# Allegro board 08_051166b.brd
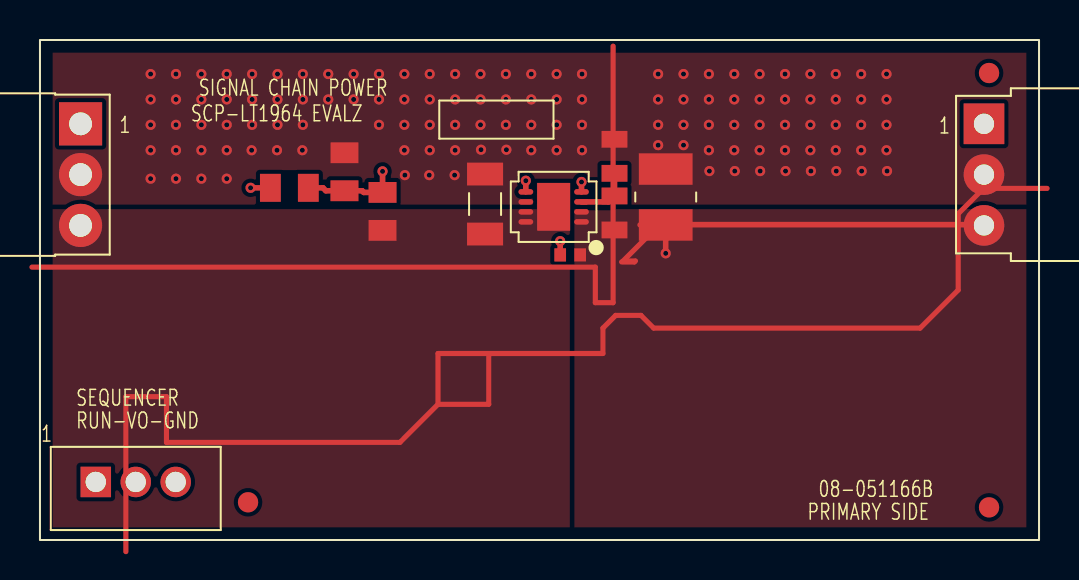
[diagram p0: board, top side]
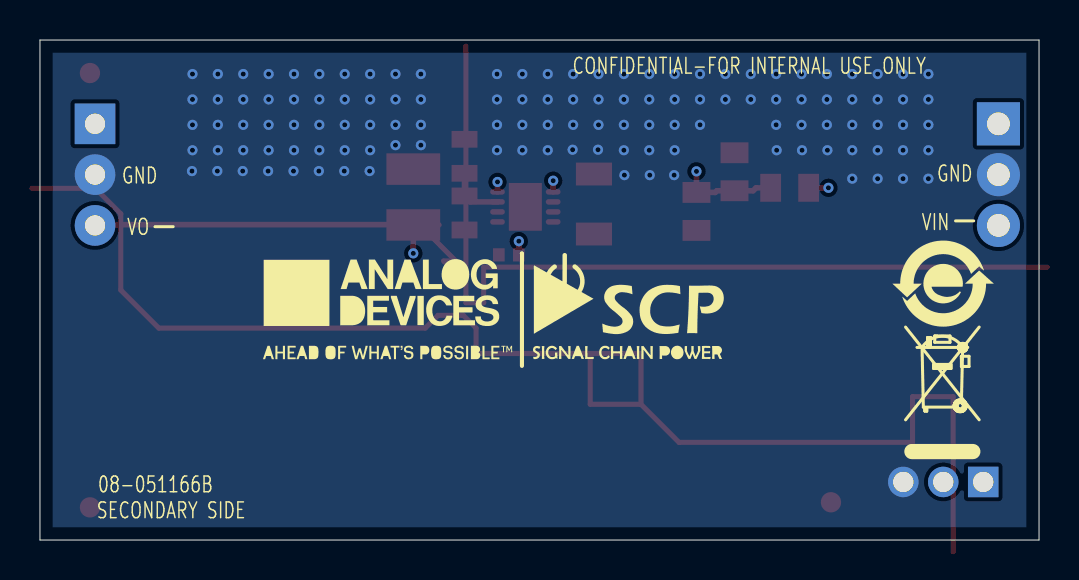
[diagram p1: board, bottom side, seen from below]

Outline 50 x 25 mm; copper layers: TOP, L2_GND, L3_SIG, BOTTOM. Coordinates in mm from the lower left corner of the outline.
Outline path: 0,25 50,25 50,0 0,0 0,25

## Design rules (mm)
constraint set DEFAULT: min track width 0.203

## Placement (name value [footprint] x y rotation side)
C3  0.01uF  [C0402]  26.54 14.26 0 top
C4  1UF  [C1206]  22.28 16.8 90 top
C5  10uF  [C1210-2]  31.32 17.15 270 top
INPUT  PBC03SBAN  [CNTHMHDRRA1X3L300W100H145]  2.03 20.81 270 top
NOREF  -  [unnamed]  47.5 23.35 0 top
NOREF#2  -  [#2]  -241.7 -190.28 0 top
NOREF#3  -  [unnamed]  10.41 1.89 0 top
NOREF#4  -  [#2]  90.79 32.31 0 top
NOREF#5  -  [#2]  -150.79 -17.34 0 top
NOREF#6  -  [#2]  -349.65 -285.95 0 top
NOREF#7  -  [#2]  41.28 3.97 0 top
NOREF#8  -  [#2]  2.03 20.81 0 top
NOREF#9  -  [#2]  -241.7 -190.28 0 top
NOREF#10  -  [#2]  -186.22 196.22 0 top
NOREF#11  -  [#2]  50 25 0 top
NOREF#12  -  [#2]  2.03 20.81 0 top
NOREF#13  -  [#2]  0 25 0 top
NOREF#14  -  [#2]  -241.7 -190.28 0 top
NOREF#15  -  [#2]  0 25 0 top
NOREF#16  -  [#2]  49.53 171.15 0 top
NOREF#17  -  [#2]  0 25 0 top
NOREF#18  -  [#2]  50 0 90 top
NOREF#19  -  [#2]  0 0 0 top
NOREF#20  -  [#2]  25.51 46.03 0 top
NOREF#21  -  [unnamed]  47.5 1.63 0 top
NOREF#22  -  [#2]  4.8 12.82 180 bottom
NOREF#23  -  [#2]  32.89 11.5 180 bottom
NOREF#24  -  [#2]  20.52 11.69 180 bottom
NOREF#25  -  [#2]  5.04 4.11 180 bottom
OUTPUT  PPPC031LGBN-RC  [CNHDRRA1X3H108]  47.24 20.81 270 top
P1  53253-0370  [CNTHMHDR1X3L315W144H224]  2.79 2.9 0 top
R1  TBD0805  [R0805#2]  12.48 17.61 0 top
R2  100K  [R0805#2]  17.14 16.43 270 top
R4  249K  [R0805]  28.75 19.18 270 top
R6  768K  [R0805]  28.75 16.35 270 top
R7  TBD0805  [R0805#2]  15.24 18.41 270 top
U1  LT1964EDD#PBF  [DFN8_3X3_PAD2_38X1_65]  25.71 16.66 90 top

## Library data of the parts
C3 = CAP: User Part Number: UPN; Tolerance: 10; alternate symbols: (); part number: CAP_SM-0.01UF,50V,10,E019413,C0402; tolerance: 10
C4 = CAP: User Part Number: UPN; Tolerance: 10; alternate symbols: (); part number: CAP_SM-1UF,25V,10,E029793,C1206; tolerance: 10
C5 = CAP: Tolerance: 5; User Part Number: UPN; alternate symbols: (); part number: CAP_SM-10UF,10V,5,E013768,C1210-2; tolerance: 5
INPUT = CN3P: Tolerance: N/A; User Part Number: UPN; alternate symbols: (CNTHMHDRRA1X3L300W100H145_SCP); part number: CN3P_TH-PBC03SBAN,E034137,CNTHMHDRRA1X3L300W100H145; tolerance: N/A
OUTPUT = CN3P: User Part Number: UPN; Tolerance: N/A; alternate symbols: (CNHDRRA1X3H108_SCP); part number: CN3P_TH-PPPC031LGBN-RC,E034111,CNHDRRA1X3H108; tolerance: N/A
P1 = CN3P: Tolerance: N/A; User Part Number: UPN; alternate symbols: (); part number: CN3P_TH-53253-0370,E033940,CNTHMHDR1X3L315W144H224; tolerance: N/A
R1 R7 = RES: User Part Number: UPN; alternate symbols: (R0805L); part number: RES_SM-TBD0805,E004051,TBD0805,TBD0805,R0805
R2 = RES: User Part Number: UPN; Tolerance: 1; alternate symbols: (R0805L); part number: RES_SM-100K,E003488,1/8W,1,R0805; tolerance: 1
R4 = RES: User Part Number: UPN; Tolerance: 1; alternate symbols: (R0805L); part number: RES_SM-249K,E033844,1/8W,1,R0805; tolerance: 1
R6 = RES: User Part Number: UPN; Tolerance: 1; alternate symbols: (R0805L); part number: RES_SM-768K,E020432,1/8W,1,R0805; tolerance: 1
U1 = LINLT1964_V2: User Part Number: UPN; Tolerance: N/A; alternate symbols: (); part number: LINLT1964_V2_SM-LT1964EDD#PBF,E034267,DFN8_3X3_PAD2_38X1_65; tolerance: N/A

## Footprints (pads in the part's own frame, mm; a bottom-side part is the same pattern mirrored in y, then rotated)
C0402
  rect 0.584x0.66 smd: 1(-0.5,0) 2(0.5,0)
C1206
  rect 1.143x1.803 smd: 1(-1.5,0) 2(1.5,0)
C1210-2
  rect 1.575x2.692 smd: 1(-1.397,0) 2(1.397,0)
CNHDRRA1X3H108
  rect 2.032x2.032 hole 1.016: 1(0,0)
  round 2.032 hole 1.016: 2(2.54,0) 3(5.08,0)
CNTHMHDR1X3L315W144H224
  rect 1.524x1.524 hole 1.016: 1(0,0)
  round 1.524 hole 1.016: 2(2,0) 3(4,0)
CNTHMHDRRA1X3L300W100H145
  rect 2.159x2.159 hole 1.143: 1(0,0)
  round 2.159 hole 1.143: 2(2.54,0) 3(5.08,0)
DFN8_3X3_PAD2_38X1_65
  oval 0.279x0.737 smd: 1(-0.75,-1.393) 2(-0.25,-1.393) 3(0.25,-1.393) 4(0.75,-1.393) 5(0.75,1.393) 6(0.25,1.393) 7(-0.25,1.393) 8(-0.75,1.393)
  rect 2.388x1.651 smd: PAD(0,0)
R0805
  rect 0.838x1.295 smd: 1(-0.85,0) 2(0.85,0)
R0805#2
  rect 1.041x1.397 smd: 1(-0.95,0) 2(0.95,0)
unnamed
  round 1.016 smd: (0,0)

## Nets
AGND: C4.2(N2) C5.1 INPUT.2 OUTPUT.2 P1.3(N3) R4.1 R7.1 U1.6
ADJ: R4.2(N2) R6.1 U1.3
SHDN: R1.2(N2) R2.1 R7.2(N2) U1.4(SHDN_N)
UNNAMED_2_CAP_I39_N1: C3.1 U1.5
UNNAMED_2_CN3P_I35_N1: P1.1 R1.1
V-: C4.1 INPUT.3(N3) R2.2(N2) U1.7 U1.8 U1.PAD
VO-: C3.2(N2) C5.2(N2) OUTPUT.3(N3) P1.2 R6.2(N2) U1.1 U1.2

Pads without a net: INPUT 1; OUTPUT 1

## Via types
v1: diameter 0.508, hole 0.254, TOP to BOTTOM, 128 vias

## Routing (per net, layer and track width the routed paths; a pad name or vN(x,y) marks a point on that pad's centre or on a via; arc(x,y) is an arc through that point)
AGND: length 0
  BOTTOM w0: 16.92,11.58 16.92,11.58
  vias: v1(5.54,23.3) v1(5.54,22.03) v1(5.54,20.76) v1(5.54,19.49) v1(5.54,18.07) v1(6.81,23.3) v1(6.81,22.03) v1(6.81,20.76) v1(6.81,19.49) v1(6.81,18.07) v1(8.08,23.3) v1(8.08,22.03) v1(8.08,20.76) v1(8.08,19.49) v1(8.08,18.07) v1(9.35,23.3) v1(9.35,22.03) v1(9.35,20.76) v1(9.35,19.49) v1(9.35,18.07) v1(10.62,23.3) v1(10.62,22.03) v1(10.62,20.76) v1(10.59,19.49) v1(11.86,19.49) v1(11.89,23.3) v1(11.89,22.03) v1(11.89,20.76) v1(13.16,23.3) v1(13.16,22.03) v1(13.16,20.76) v1(13.13,19.49) v1(14.43,23.3) v1(14.43,22.03) v1(15.7,23.3) v1(15.7,22.03) v1(16.97,23.3) v1(16.97,22.03) v1(16.97,20.76) v1(18.24,23.3) v1(18.24,22.03) v1(18.24,20.76) v1(18.24,19.49) v1(18.26,18.24) v1(19.48,18.24) v1(19.51,23.3) v1(19.51,22.03) v1(19.51,20.76) v1(19.51,19.49) v1(20.78,23.3) v1(20.78,22.03) v1(20.78,20.76) v1(20.78,19.49) v1(20.75,18.24) v1(22.05,23.3) v1(22.05,22.03) v1(22.05,20.76) v1(22.07,19.51) v1(23.32,23.3) v1(23.32,22.03) v1(23.32,20.76) v1(23.34,19.51) v1(24.59,23.3) v1(24.59,22.03) v1(24.59,20.76) v1(24.59,19.49) v1(25.86,23.3) v1(25.86,22.03) v1(25.86,20.76) v1(25.86,19.49) v1(27.13,23.3) v1(27.13,22.03) v1(27.13,20.76) v1(27.13,19.49) v1(30.94,23.3) v1(30.94,22.03) v1(30.94,20.76) v1(30.94,19.74) v1(32.21,23.3) v1(32.21,22.03) v1(32.21,20.76) v1(32.21,19.74) v1(33.48,23.3) v1(33.48,22.03) v1(33.48,20.76) v1(33.48,19.49) v1(33.5,18.45) v1(34.75,23.3) v1(34.75,22.03) v1(34.75,20.76) v1(34.75,19.49) v1(34.77,18.45) v1(36.02,23.3) v1(36.02,22.03) v1(36.02,20.76) v1(36.02,19.49) v1(36.04,18.45) v1(37.29,23.3) v1(37.29,22.03) v1(37.29,20.76) v1(37.29,19.49) v1(37.31,18.45) v1(38.56,23.3) v1(38.56,22.03) v1(38.56,20.76) v1(38.56,19.49) v1(38.58,18.45) v1(39.83,23.3) v1(39.83,22.03) v1(39.83,20.76) v1(39.83,19.49) v1(39.85,18.45) v1(41.1,23.3) v1(41.1,22.03) v1(41.1,20.76) v1(41.1,19.49) v1(41.12,18.45) v1(42.37,23.3) v1(42.37,22.03) v1(42.37,20.76) v1(42.37,19.49) v1(42.39,18.45)
ADJ: length 2.9
  TOP w0.279: U1.3 28.46,16.91 R6.1 R4.2
SHDN: length 15.9
  TOP w0.279: R1.2 14.16,17.61 14.31,17.46 R7.2 16.12,17.46 16.2,17.38 17.14,17.38 v1(17.14,18.43) ; U1.4 v1(27.1,17.9)
  L3_SIG w0.279: v1(27.1,17.9) 26.11,18.89 17.6,18.89 v1(17.14,18.43)
UNNAMED_2_CAP_I39_N1: length 5
  TOP w0.279: C3.1 v1(26.04,14.94) ; U1.5 v1(24.32,17.96)
  L3_SIG w0.279: v1(26.04,14.94) 26.04,16.24 v1(24.32,17.96)
UNNAMED_2_CN3P_I35_N1: length 18.9
  TOP w0.279: R1.1 v1(10.54,17.61)
  L3_SIG w0.279: P1.1 2.79,6.84 10.54,14.59 v1(10.54,17.61)
VO-: length 33.6
  TOP w0.279: C5.2 v1(31.32,14.33)
  L3_SIG w0.279: P1.2 12.77,10.88 29.44,10.88 31.32,12.76 v1(31.32,14.33)

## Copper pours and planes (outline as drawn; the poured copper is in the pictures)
AGND on TOP: 0.64,24.37 49.36,24.36 49.36,16.77 0.64,16.77 ; 2 cut-outs
AGND on BOTTOM, L2_GND, L3_SIG: 0.64,0.64 0.64,24.36 49.36,24.36 49.36,0.64
V- on TOP: 24.87,17.86 26.52,17.86 26.52,14.99 26.37,15.12 26.19,15.17 25.79,14.76 26.19,14.36 26.37,14.41 26.52,14.54 26.52,0.64 0.64,0.64 0.64,16.54 24.87,16.54
VO- on TOP: 26.75,16.54 49.36,16.54 49.36,0.64 26.75,0.64

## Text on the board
Ref Des/Silkscreen Bottom: GND | VIN | CONFIDENTIAL-FOR INTERNAL USE ONLY | 08-051166B | VO | -
User.Comments: 4.    RoHS COMPLIANCE: ASSEMBLY VENDOR SHOULD ASSURE COMPLIANCE | WITH LEAD-FREE AND RoHS PCB ASSEMBLY STANDARDS (EU RoHS | DIRECTIVE 2002/95/EC).
Ref Des/Silkscreen Top: SEQUENCER | RUN-VO-GND | SCP-LT1964 EVALZ | SIGNAL CHAIN POWER
PAGE_OUTLINE: N/A | A.CAUILAN | K.JABATAN | J.M.PLAZA | J.VIERNES | 10OCT18 | A | B | AS PER ECR-086420 | 06DEC18 | 07MAY19 | SCP-LT1964 EVALZ | EVALUATION BOARD | -051166
DIMENSION: REF | SEE FAB NOTES 15 | DIA MAX
User.15: ROHS COMPLIANCE NOTE:  (Required for Customer Boards) Add to top of MATERIALS | ENIG (Electroless Nickel/Immersion Gold) | PER IPC-4552 LATEST REVISION | HOMOGENOUS MATERIALS IN THIS BOARD SHALL BE COMPLIANT | THE EU RoHS DIRECTIVE 2002/95/EC | 15.    THRU VIAS TO BE FILLED WITH SOLDERMASK.
User.17: L2 GND | 08-      -07
User.18: L3 GND | 08-      -08
User.23: 2 | B
User.24: 2 | A
User.27: 2 | B
User.45: 2 | FIGURE | SIZE | 10.0 | 40.0 | 45.0 | PLATED | FINISHED HOLES IN MILS | ALL UNITS ARE IN MILS | QTY | 128 | 6 | 3 | TOLERANCE/NOTES | EVALUATION BOARD | B
